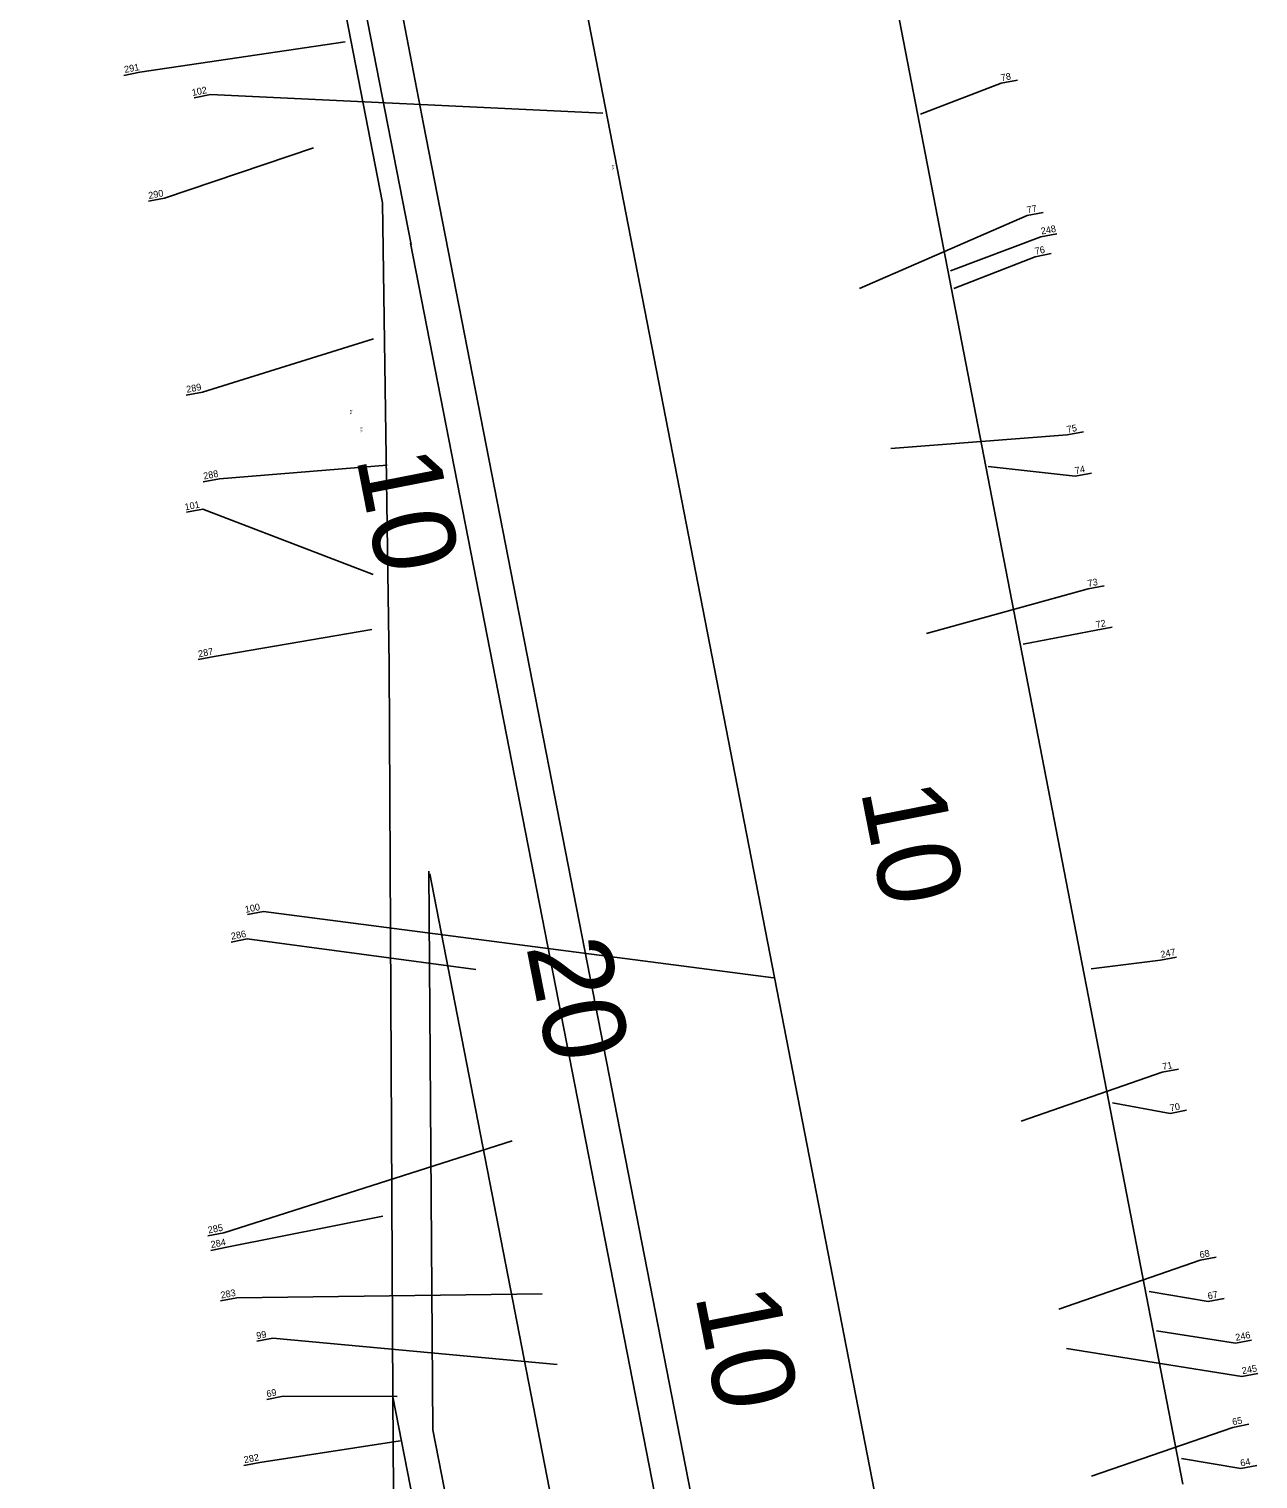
# Model space of a CAD drawing. Extents: x -545967 to -545044, y -1122650 to -1118491.
# Drawn here: x -545716.4 to -545377.2, y -1120101.4 to -1119701.2 of the extents above; entities that cross this region are included whole.
import ezdxf

# ---------------------------------------------------------------- set-up
doc = ezdxf.new("R2010")
doc.units = 0
for name, color, linetype in [('osvětlené plochy-hodnota-obrys', 7, 'Continuous'), ('so180602', 7, 'Continuous'), ('Vrstva 63', 7, 'Continuous')]:
    doc.layers.add(name, color=color, linetype=linetype)

msp = doc.modelspace()

# ---------------------------------------------------------------- linework, layer by layer
at = {"layer": 'osvětlené plochy-hodnota-obrys'}
for points in [[(-545716.39, -1119223.72), (-545705.99, -1119221.66), (-545669.44, -1119408.76), (-545659.4, -1119462.63), (-545647.69, -1119521.35), (-545640.52, -1119558.73), (-545633.58, -1119589.7), (-545629.52, -1119613.81), (-545623.04, -1119645.06), (-545619.03, -1119667.56), (-545607.52, -1119727.52)], [(-545610.9, -1119760.66), (-545622.84, -1119699.49), (-545637.26, -1119626.87), (-545653.54, -1119543.45), (-545716.39, -1119223.72)], [(-545520.97, -1119506.47), (-545505.64, -1119546.72), (-545397.93, -1120102.85)], [(-545618.79, -1119749.17), (-545664.28, -1119515.64)], [(-545441.66, -1120319.91), (-545444.67, -1120302.28), (-545584.85, -1119581.02)], [(-545607.52, -1119727.52), (-545482.54, -1120367.87), (-545465.73, -1120446.74)], [(-545618.79, -1119749.17), (-545617, -1119876.72)], [(-545611.11, -1119760.37), (-545492.39, -1120368.61), (-545475.58, -1120447.49)], [(-545615.95, -1120078.59), (-545617, -1119876.72)], [(-545604.97, -1120087.82), (-545606.01, -1119933.66)], [(-545605.8, -1119934.36), (-545489.14, -1120534.59)], [(-545587.34, -1120327.06), (-545598.8, -1120329.21), (-545624.38, -1120192.88), (-545623.87, -1120152.06), (-545615.74, -1120117.75), (-545615.95, -1120078.59)], [(-545615.95, -1120078.72), (-545593.53, -1120193.57), (-545569.43, -1120317.04), (-545566.21, -1120328.42), (-545557.45, -1120326.08), (-545560.55, -1120315.17), (-545604.97, -1120087.82)]]:
    msp.add_lwpolyline(points, dxfattribs=at)
at = {"layer": 'Vrstva 63'}
for p, q in [((-545629.16, -1119704.74), (-545685.8, -1119713.16)), ((-545685.8, -1119713.16), (-545690.25, -1119714.03)), ((-545443.63, -1119715.35), (-545448.07, -1119716.21)), ((-545666.34, -1119719.32), (-545670.78, -1119720.19)), ((-545558.01, -1119724.49), (-545666.34, -1119719.32)), ((-545448.07, -1119716.21), (-545470.36, -1119724.7)), ((-545637.91, -1119734.03), (-545679, -1119747.92)), ((-545679, -1119747.92), (-545683.44, -1119748.78)), ((-545440.93, -1119752.7), (-545487.17, -1119772.85)), ((-545436.49, -1119751.84), (-545440.93, -1119752.7)), ((-545437.15, -1119758.61), (-545462.07, -1119767.98)), ((-545432.71, -1119757.74), (-545437.15, -1119758.61)), ((-545432.71, -1119757.74), (-545437.15, -1119758.61)), ((-545432.71, -1119757.74), (-545437.15, -1119758.61)), ((-545434.26, -1119763.21), (-545438.7, -1119764.07)), ((-545438.7, -1119764.07), (-545461.14, -1119772.83)), ((-545621.33, -1119786.75), (-545668.53, -1119801.41)), ((-545668.53, -1119801.41), (-545672.98, -1119802.27)), ((-545429.86, -1119813.27), (-545478.55, -1119817.02)), ((-545425.42, -1119812.41), (-545429.86, -1119813.27)), ((-545617.53, -1119821.58), (-545663.85, -1119825.34)), ((-545427.64, -1119824.64), (-545451.69, -1119821.93)), ((-545663.85, -1119825.34), (-545668.29, -1119826.2)), ((-545423.19, -1119823.78), (-545427.64, -1119824.64)), ((-545668.45, -1119833.74), (-545672.9, -1119834.6)), ((-545621.41, -1119851.76), (-545668.45, -1119833.74)), ((-545419.69, -1119854.91), (-545424.13, -1119855.77)), ((-545424.13, -1119855.77), (-545468.71, -1119868.1)), ((-545621.77, -1119866.96), (-545665.26, -1119874.41)), ((-545421.91, -1119867.14), (-545442.02, -1119870.98)), ((-545417.46, -1119866.28), (-545421.91, -1119867.14)), ((-545665.26, -1119874.41), (-545669.71, -1119875.27)), ((-545651.67, -1119944.77), (-545656.11, -1119945.63)), ((-545510.94, -1119963.06), (-545651.67, -1119944.77)), ((-545656.19, -1119952.35), (-545660.64, -1119953.21)), ((-545593.07, -1119960.74), (-545656.19, -1119952.35)), ((-545404.16, -1119958.23), (-545423.25, -1119960.58)), ((-545399.71, -1119957.36), (-545404.16, -1119958.23)), ((-545399.71, -1119957.36), (-545404.16, -1119958.23)), ((-545399.71, -1119957.36), (-545404.16, -1119958.23)), ((-545403.65, -1119989.15), (-545442.61, -1120002.62)), ((-545399.2, -1119988.28), (-545403.65, -1119989.15)), ((-545401.42, -1120000.52), (-545417.42, -1119997.61)), ((-545396.98, -1119999.65), (-545401.42, -1120000.52)), ((-545583.04, -1120008.07), (-545662.59, -1120033.42)), ((-545618.71, -1120028.82), (-545661.8, -1120037.43)), ((-545662.59, -1120033.42), (-545667.03, -1120034.28)), ((-545661.8, -1120037.43), (-545666.25, -1120038.29)), ((-545393.23, -1120041.04), (-545432.2, -1120054.51)), ((-545388.79, -1120040.18), (-545393.23, -1120041.04)), ((-545659.07, -1120051.4), (-545663.51, -1120052.26)), ((-545574.8, -1120050.3), (-545659.07, -1120051.4)), ((-545391.01, -1120052.41), (-545407.3, -1120049.64)), ((-545386.56, -1120051.55), (-545391.01, -1120052.41)), ((-545649.08, -1120062.54), (-545653.53, -1120063.4)), ((-545570.64, -1120069.81), (-545649.08, -1120062.54)), ((-545383.47, -1120063.91), (-545405.2, -1120060.48)), ((-545379.03, -1120063.04), (-545383.47, -1120063.91)), ((-545379.03, -1120063.04), (-545383.47, -1120063.91)), ((-545379.03, -1120063.04), (-545383.47, -1120063.91)), ((-545381.67, -1120073.11), (-545430.08, -1120065.36)), ((-545377.23, -1120072.25), (-545381.67, -1120073.11)), ((-545377.23, -1120072.25), (-545381.67, -1120073.11)), ((-545377.23, -1120072.25), (-545381.67, -1120073.11)), ((-545646.29, -1120078.57), (-545650.74, -1120079.44)), ((-545614.76, -1120078.64), (-545646.29, -1120078.57)), ((-545384.2, -1120087.17), (-545423.19, -1120100.63)), ((-545379.76, -1120086.3), (-545384.2, -1120087.17)), ((-545613.92, -1120090.9), (-545652.65, -1120096.8)), ((-545652.65, -1120096.8), (-545657.1, -1120097.66)), ((-545381.98, -1120098.54), (-545398.35, -1120095.77)), ((-545377.54, -1120097.67), (-545381.98, -1120098.54))]:
    msp.add_line(p, q, dxfattribs=at)

# ---------------------------------------------------------------- texts
at = {"layer": 'osvětlené plochy-hodnota-obrys'}
for s, p in [('10', (-545626.16, -1119819.49)), ('10', (-545486.94, -1119911.28)), ('20', (-545579.21, -1119954.41)), ('10', (-545532.61, -1120050.58))]:
    msp.add_text(s, height=22.781, rotation=281.0956, dxfattribs=at).set_placement(p)
at = {"layer": 'so180602'}
for s, p in [('291', (-545689.92, -1119713.36)), ('78', (-545448.01, -1119715.63)), ('102', (-545671.26, -1119719.71)), ('290', (-545683.26, -1119748.15)), ('77', (-545440.86, -1119752.12)), ('248', (-545436.96, -1119757.97)), ('76', (-545438.64, -1119763.49)), ('289', (-545672.79, -1119801.64)), ('75', (-545429.8, -1119812.69)), ('288', (-545668.1, -1119825.57)), ('74', (-545427.58, -1119824.06)), ('101', (-545673.25, -1119834.1)), ('73', (-545424.07, -1119855.19)), ('72', (-545421.83, -1119866.56)), ('287', (-545669.5, -1119874.64)), ('100', (-545656.61, -1119945.16)), ('286', (-545660.45, -1119952.57)), ('247', (-545403.95, -1119957.59)), ('71', (-545403.45, -1119988.54)), ('70', (-545401.36, -1119999.94)), ('285', (-545666.84, -1120033.65)), ('284', (-545666.06, -1120037.66)), ('68', (-545393.17, -1120040.46)), ('283', (-545663.32, -1120051.62)), ('67', (-545390.93, -1120051.83)), ('99', (-545653.46, -1120062.82)), ('246', (-545383.28, -1120063.27)), ('245', (-545381.48, -1120072.48)), ('69', (-545650.67, -1120078.86)), ('65', (-545384.14, -1120086.59)), ('282', (-545656.9, -1120097.02)), ('64', (-545381.92, -1120097.96))]:
    msp.add_text(s, height=1.875, rotation=10.9955, dxfattribs=at).set_placement(p)
at = {"layer": 'Vrstva 63'}
for height, rotation, p in [(0.686, 278.6291, (-545555.6, -1119738.79)), (0.679, 270.8539, (-545627.82, -1119806.34)), (0.685, 277.4807, (-545625, -1119811.18))]:
    msp.add_text('k.s.', height=height, rotation=rotation, dxfattribs=at).set_placement(p)

doc.saveas('drawing.dxf')
